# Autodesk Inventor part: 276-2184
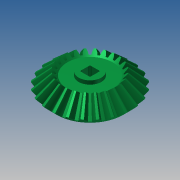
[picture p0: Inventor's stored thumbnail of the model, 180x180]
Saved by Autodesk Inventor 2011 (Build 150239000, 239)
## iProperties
Created: 2010-04
Part Number: 276-2184
Material: ABS Plastic
Document SubType Name: Modeling
Designer: Autodesk Inc.
Categories: <?xml version="1.0" encoding="UTF-16"?> <MemberInstance><Categories><FamilyTemplate><FamilyTemplateParameter ValueType="xs:double" Id="1" ObjectReferenceKey="da
Mass: 1.68349 g
Surface Area: 21.9898 cm^2
Volume: 1.58819 cm^3
Density: 1.06 g/cm^3
Catalog Web Link: http://www.vexrobotics.com/276-2184.html
Vendor: Innovation First, Inc.
CustomPartVersion: 1
Company: Autodesk Inc.
Author: Autodesk Inc.
Title: VEX Robotics Kit of Parts
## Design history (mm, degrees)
node "Top Point"
node "Mesh Plane2"
sketch "Teeth Body Sketch"
  geometry: L1 (0, 0)-(11.802, -13.598); L2 (11.802, -13.598)-(13.448, -11.952); L3 (13.448, -11.952)-(0, 0); L4 (12.7, -12.7)-(0, 0); L5 (7.629, -8.79)-(8.694, -7.726); L6 (11.802, -13.598)-(7.629, -8.79); L7 (13.448, -11.952)-(8.694, -7.726); L8 (0, -39.387)-(0, 6.564) reference; L9 (0, -12.7)-(13.448, -12.7)
  constraints: 16 end point, 4 point on line, 3 perpendicular, 2 collinear, 1 horizontal alignment, 1 vertical alignment
  dimensions: "d0" = 25.4 diameter of L4.start L8 (= da_de); "d1" = 23.60395 diameter of L1.end L8 (= da_dfe); "d2" = 26.89671 diameter of L2.end L8 (= da_dae); "d3" = 6.35 distance between parallel lines of L2 L5 (= da_b); "d4" = 11.95165 vertical distance of L2.end L1.start (= da_ve)
revolve "Teeth Body" sketch "Teeth Body Sketch" stored, may be unused: angle "d5" = 90 deg
node "Start Point"
node "Tooth Plane"
sketch "Start Sketch"
  geometry: L1 (0, -23.505)-(0, 10.645) reference; L2 (-0.4, -1.549)-(0.4, -1.549); A1 r 6.505 centre (-6.831, -2.533) between (-0.4, -1.549) and (-1.864, 1.669); A2 r 6.505 centre (6.831, -2.533) between (1.864, 1.669) and (0.4, -1.549); A3 r 19.717 centre (0, -17.961) between (1.864, 1.669) and (-1.864, 1.669); 1 further point
  constraints: 6 point on circle, 3 centre point, 3 symmetric about line, 2 end point, 1 coincident, 1 perpendicular, 1 other
  dimensions: "d7" = 6.50483 radius of A1 (= fd_rr); "d8" = 6.83059 horizontal distance of point (0, -17.961) A1.centre (= fd_x); "d9" = 15.42797 vertical distance of point (0, -17.961) A1.centre (= fd_y); "d57" = 19.71735 radius of A3 (= 0.5 x fd_dva + 0.3 x da_he); "d58" = 16.41111 distance from line of A3.centre L2 (= 0.5 x fd_dva - 1.12 x da_he)
node "End Point"
  node "End Plane"
sketch "3D Sketch Right"
  node "Helical Curve Right" dims "d65" = 127.62048 (computed from da_dm, da_delta, da_beta), "d66" = 31.5, "d67" = 25.4 (= da_de), "d68" = -45 deg (= -da_delta), "d69" = 4.57245 (computed from fd_loft, da_delta)
node "End Plane Right"
sketch "End Sketch Right"
  geometry: L1 (0, -18.196)-(0, 9.82) reference; L2 (-0.257, -0.975)-(0.257, -0.975); A1 r 4.169 centre (-4.378, -1.605) between (-0.257, -0.975) and (-1.195, 1.087); A2 r 4.169 centre (4.378, -1.605) between (1.195, 1.087) and (0.257, -0.975); A3 r 12.638 centre (0, -11.494) between (1.195, 1.087) and (-1.195, 1.087); 1 further point
  constraints: 6 point on circle, 3 centre point, 3 symmetric about line, 2 end point, 1 coincident, 1 perpendicular, 1 other
  dimensions: "d70" = 4.37817 horizontal distance of A3.centre A1.centre (computed from fd_x, fd_ratio); "d71" = 9.88879 vertical distance of point (0, -11.494) A1.centre (computed from fd_y, fd_ratio); "d72" = 4.16937 radius of A1 (computed from fd_rr, fd_ratio); "d73" = 10.51895 distance from line of point (0, -11.494) L2 (computed from d58, fd_ratio); "d74" = 12.63812 radius of A3 (computed from d57, fd_ratio)
feature "Loft Right" sketch "End Sketch Right" dims "d75" = 0, "d76" = 90 deg, "d77" = 0, "d78" = 90 deg, "d79" = 0, "d80" = 90 deg, "d85" = 20, "da_teethtype" = 0 [user parameter]
sketch "3D Sketch Left"
  node "Helical Curve Left" dims "d26" = 127.62048 (computed from da_dm, da_delta, da_beta), "d27" = 4.57245 (computed from fd_loft, da_delta), "d28" = 25.4 (= da_de), "d29" = -45 deg (= -da_delta)
node "End Plane Left"
sketch "End Sketch Left" dims "d56" = 6.1486 (derived)
  geometry: L1 (0, -31.428)-(0, 14.43) reference; L2 (-0.257, -0.973)-(0.257, -0.973); A1 r 4.169 centre (-4.378, -1.603) between (-0.257, -0.973) and (-1.195, 1.09); A2 r 4.169 centre (4.378, -1.603) between (1.195, 1.09) and (0.257, -0.973); A3 r 12.638 centre (0, -11.492) between (1.195, 1.09) and (-1.195, 1.09); 2 further points; 1 other entity
  constraints: 6 point on circle, 3 centre point, 3 symmetric about line, 2 end point, 1 coincident, 2 other
  dimensions: "d30" = 4.16937 radius of A1 (computed from fd_rr, fd_ratio); "d31" = 4.37817 horizontal distance of point (0, -11.492) A1.centre (computed from fd_x, fd_ratio); "d32" = 9.88879 vertical distance of A1.centre point (0, -11.492) (computed from fd_y, fd_ratio); "d61" = 12.63812 radius of A3 (computed from d57, fd_ratio); "d62" = 10.51895 distance from line of point (0, -11.492) L2 (computed from d58, fd_ratio)
feature "Loft Left" sketch "End Sketch Left" dims "d35" = 0, "d37" = 0, "d39" = 0, "d40" = 90 deg, "d63" = 90 deg, "d64" = 90 deg, "d84" = 10, "da_teethtype" = 0 [user parameter]
sketch "Body Sketch"
  geometry: L1 (0, -35.038)-(0, -19.531) reference; L2 (11.802, -13.598)-(7.629, -8.79) reference; L3 (7.629, -8.79)-(0, -8.79); L4 (11.802, -13.598)-(0, -13.598)
  constraints: 4 end point, 2 perpendicular, 2 point on line
revolve "Fix Body" sketch "Body Sketch" stored, may be unused: angle "d46" = 90 deg
sketch "Sketch6"
  geometry: L1 (12.7, -12.7)-(0, 0) reference; L2 (0, -37.8)-(0, 6.3) reference
feature "Pitch Diameter" sketch "Sketch6" dims angle "d47" = 90 deg
sketch "Sketch8"
  geometry: A1 r 7.629 centre (0, 0) between (0.287, 7.624) and (-0.287, 7.624) reference; A2 r 7.629 centre (0, 0) between (-0.287, 7.624) and (-1.696, 7.438) reference; A3 r 7.629 centre (0, 0) between (-1.696, 7.438) and (-2.25, 7.29) reference; A4 r 7.629 centre (0, 0) between (-2.25, 7.29) and (-3.564, 6.746) reference; A5 r 7.629 centre (0, 0) between (-3.564, 6.746) and (-4.06, 6.459) reference; A6 r 7.629 centre (0, 0) between (-4.06, 6.459) and (-5.188, 5.594) reference; A7 r 7.629 centre (0, 0) between (-5.188, 5.594) and (-5.594, 5.188) reference; A8 r 7.629 centre (0, 0) between (-5.594, 5.188) and (-6.459, 4.06) reference; A9 r 7.629 centre (0, 0) between (-6.459, 4.06) and (-6.746, 3.564) reference; A10 r 7.629 centre (0, 0) between (-6.746, 3.564) and (-7.29, 2.25) reference; A11 r 7.629 centre (0, 0) between (-7.29, 2.25) and (-7.438, 1.696) reference; A12 r 7.629 centre (0, 0) between (-7.438, 1.696) and (-7.624, 0.287) reference; A13 r 7.629 centre (0, 0) between (-7.624, 0.287) and (-7.624, -0.287) reference; A14 r 7.629 centre (0, 0) between (-7.624, -0.287) and (-7.438, -1.696) reference; A15 r 7.629 centre (0, 0) between (-7.438, -1.696) and (-7.29, -2.25) reference; A16 r 7.629 centre (0, 0) between (-7.29, -2.25) and (-6.746, -3.564) reference; A17 r 7.629 centre (0, 0) between (-6.746, -3.564) and (-6.459, -4.06) reference; A18 r 7.629 centre (0, 0) between (-6.459, -4.06) and (-5.594, -5.188) reference; A19 r 7.629 centre (0, 0) between (-5.594, -5.188) and (-5.188, -5.594) reference; A20 r 7.629 centre (0, 0) between (-5.188, -5.594) and (-4.06, -6.459) reference; A21 r 7.629 centre (0, 0) between (-4.06, -6.459) and (-3.564, -6.746) reference; A22 r 7.629 centre (0, 0) between (-3.564, -6.746) and (-2.25, -7.29) reference; A23 r 7.629 centre (0, 0) between (-2.25, -7.29) and (-1.696, -7.438) reference; A24 r 7.629 centre (0, 0) between (-1.696, -7.438) and (-0.287, -7.624) reference; A25 r 7.629 centre (0, 0) between (-0.287, -7.624) and (0.287, -7.624) reference; A26 r 7.629 centre (0, 0) between (0.287, -7.624) and (1.696, -7.438) reference; A27 r 7.629 centre (0, 0) between (1.696, -7.438) and (2.25, -7.29) reference; A28 r 7.629 centre (0, 0) between (2.25, -7.29) and (3.564, -6.746) reference; A29 r 7.629 centre (0, 0) between (3.564, -6.746) and (4.06, -6.459) reference; A30 r 7.629 centre (0, 0) between (4.06, -6.459) and (5.188, -5.594) reference; A31 r 7.629 centre (0, 0) between (5.188, -5.594) and (5.594, -5.188) reference; A32 r 7.629 centre (0, 0) between (5.594, -5.188) and (6.459, -4.06) reference; A33 r 7.629 centre (0, 0) between (6.459, -4.06) and (6.746, -3.564) reference; A34 r 7.629 centre (0, 0) between (6.746, -3.564) and (7.29, -2.25) reference; A35 r 7.629 centre (0, 0) between (7.29, -2.25) and (7.438, -1.696) reference; A36 r 7.629 centre (0, 0) between (7.438, -1.696) and (7.624, -0.287) reference; A37 r 7.629 centre (0, 0) between (7.624, -0.287) and (7.624, 0.287) reference; A38 r 7.629 centre (0, 0) between (7.624, 0.287) and (7.438, 1.696) reference; A39 r 7.629 centre (0, 0) between (7.438, 1.696) and (7.29, 2.25) reference; A40 r 7.629 centre (0, 0) between (7.29, 2.25) and (6.746, 3.564) reference; A41 r 7.629 centre (0, 0) between (6.746, 3.564) and (6.459, 4.06) reference; A42 r 7.629 centre (0, 0) between (6.459, 4.06) and (5.594, 5.188) reference; A43 r 7.629 centre (0, 0) between (5.594, 5.188) and (5.188, 5.594) reference; A44 r 7.629 centre (0, 0) between (5.188, 5.594) and (4.06, 6.459) reference; A45 r 7.629 centre (0, 0) between (4.06, 6.459) and (3.564, 6.746) reference; A46 r 7.629 centre (0, 0) between (3.564, 6.746) and (2.25, 7.29) reference; A47 r 7.629 centre (0, 0) between (2.25, 7.29) and (1.696, 7.438) reference; A48 r 7.629 centre (0, 0) between (1.696, 7.438) and (0.287, 7.624) reference
extrude "Extrusion1" cut sketch "Sketch8" distance "d90" = 0.3556; taper "d91" = -45 deg
sketch "Sketch9"
  geometry: A1 r 11.802 centre (0, 0) between (0.448, 11.793) and (-0.448, 11.793) reference; A2 r 11.802 centre (0, 0) between (-0.448, 11.793) and (-2.62, 11.508) reference; A3 r 11.802 centre (0, 0) between (-2.62, 11.508) and (-3.485, 11.276) reference; A4 r 11.802 centre (0, 0) between (-3.485, 11.276) and (-5.509, 10.437) reference; A5 r 11.802 centre (0, 0) between (-5.509, 10.437) and (-6.285, 9.989) reference; A6 r 11.802 centre (0, 0) between (-6.285, 9.989) and (-8.022, 8.656) reference; A7 r 11.802 centre (0, 0) between (-8.022, 8.656) and (-8.656, 8.022) reference; A8 r 11.802 centre (0, 0) between (-8.656, 8.022) and (-9.989, 6.285) reference; A9 r 11.802 centre (0, 0) between (-9.989, 6.285) and (-10.437, 5.509) reference; A10 r 11.802 centre (0, 0) between (-10.437, 5.509) and (-11.276, 3.485) reference; A11 r 11.802 centre (0, 0) between (-11.276, 3.485) and (-11.508, 2.62) reference; A12 r 11.802 centre (0, 0) between (-11.508, 2.62) and (-11.793, 0.448) reference; A13 r 11.802 centre (0, 0) between (-11.793, 0.448) and (-11.793, -0.448) reference; A14 r 11.802 centre (0, 0) between (-11.793, -0.448) and (-11.508, -2.62) reference; A15 r 11.802 centre (0, 0) between (-11.508, -2.62) and (-11.276, -3.485) reference; A16 r 11.802 centre (0, 0) between (-11.276, -3.485) and (-10.437, -5.509) reference; A17 r 11.802 centre (0, 0) between (-10.437, -5.509) and (-9.989, -6.285) reference; A18 r 11.802 centre (0, 0) between (-9.989, -6.285) and (-8.656, -8.022) reference; A19 r 11.802 centre (0, 0) between (-8.656, -8.022) and (-8.022, -8.656) reference; A20 r 11.802 centre (0, 0) between (-8.022, -8.656) and (-6.285, -9.989) reference; A21 r 11.802 centre (0, 0) between (-6.285, -9.989) and (-5.509, -10.437) reference; A22 r 11.802 centre (0, 0) between (-5.509, -10.437) and (-3.485, -11.276) reference; A23 r 11.802 centre (0, 0) between (-3.485, -11.276) and (-2.62, -11.508) reference; A24 r 11.802 centre (0, 0) between (-2.62, -11.508) and (-0.448, -11.793) reference; A25 r 11.802 centre (0, 0) between (-0.448, -11.793) and (0.448, -11.793) reference; A26 r 11.802 centre (0, 0) between (0.448, -11.793) and (2.62, -11.508) reference; A27 r 11.802 centre (0, 0) between (2.62, -11.508) and (3.485, -11.276) reference; A28 r 11.802 centre (0, 0) between (3.485, -11.276) and (5.509, -10.437) reference; A29 r 11.802 centre (0, 0) between (5.509, -10.437) and (6.285, -9.989) reference; A30 r 11.802 centre (0, 0) between (6.285, -9.989) and (8.022, -8.656) reference; A31 r 11.802 centre (0, 0) between (8.022, -8.656) and (8.656, -8.022) reference; A32 r 11.802 centre (0, 0) between (8.656, -8.022) and (9.989, -6.285) reference; A33 r 11.802 centre (0, 0) between (9.989, -6.285) and (10.437, -5.509) reference; A34 r 11.802 centre (0, 0) between (10.437, -5.509) and (11.276, -3.485) reference; A35 r 11.802 centre (0, 0) between (11.276, -3.485) and (11.508, -2.62) reference; A36 r 11.802 centre (0, 0) between (11.508, -2.62) and (11.793, -0.448) reference; A37 r 11.802 centre (0, 0) between (11.793, -0.448) and (11.793, 0.448) reference; A38 r 11.802 centre (0, 0) between (11.793, 0.448) and (11.508, 2.62) reference; A39 r 11.802 centre (0, 0) between (11.508, 2.62) and (11.276, 3.485) reference; A40 r 11.802 centre (0, 0) between (11.276, 3.485) and (10.437, 5.509) reference; A41 r 11.802 centre (0, 0) between (10.437, 5.509) and (9.989, 6.285) reference; A42 r 11.802 centre (0, 0) between (9.989, 6.285) and (8.656, 8.022) reference; A43 r 11.802 centre (0, 0) between (8.656, 8.022) and (8.022, 8.656) reference; A44 r 11.802 centre (0, 0) between (8.022, 8.656) and (6.285, 9.989) reference; A45 r 11.802 centre (0, 0) between (6.285, 9.989) and (5.509, 10.437) reference; A46 r 11.802 centre (0, 0) between (5.509, 10.437) and (3.485, 11.276) reference; A47 r 11.802 centre (0, 0) between (3.485, 11.276) and (2.62, 11.508) reference; A48 r 11.802 centre (0, 0) between (2.62, 11.508) and (0.448, 11.793) reference
extrude "Extrusion2" join sketch "Sketch9" distance "d92" = 1.1176; taper "d93" = -45 deg
sketch "Sketch10"
  geometry: C1 r 7.274 at (0, 0) reference; C2 r 3.632 at (0, 0)
  constraints: 1 centre point, 1 coincident
  dimensions: "d94" = 7.2644 diameter of C2
extrude "Extrusion3" join sketch "Sketch10" distance "d95" = 9.525; taper "d96" = 0 deg
extrude "Extrusion4" join sketch "Sketch10" distance "d97" = 1.1938; taper "d98" = 0 deg
sketch "Sketch11"
  geometry: L1 (1.612, 0.952)-(1.558, 1.007); L2 (1.558, 1.025)-(1.612, 1.079); L3 (1.612, 1.104)-(1.612, 1.079); L4 (1.558, 1.177)-(1.612, 1.231); L5 (1.612, 1.362)-(1.612, 1.231); L6 (1.232, 1.612)-(1.177, 1.558); L7 (1.159, 1.558)-(1.105, 1.612); L8 (1.079, 1.612)-(1.105, 1.612); L9 (1.232, 1.612)-(1.362, 1.612); L10 (1.612, 0.952)-(1.612, -0.952); L11 (1.558, -1.007)-(1.612, -0.952); L12 (1.612, 1.104)-(1.558, 1.159); L13 (1.079, 1.612)-(1.025, 1.558); L14 (-1.362, 1.612)-(-1.231, 1.612); L15 (-1.177, 1.558)-(-1.231, 1.612); L16 (1.007, 1.558)-(0.952, 1.612); L17 (-0.952, 1.613)-(0.952, 1.612); L18 (-0.952, 1.613)-(-1.007, 1.558); L19 (-1.024, 1.558)-(-1.079, 1.612); L20 (-1.104, 1.613)-(-1.079, 1.612); L21 (-1.104, 1.613)-(-1.159, 1.558); L22 (1.613, -1.079)-(1.558, -1.024); L23 (1.613, -1.079)-(1.612, -1.105); L24 (1.558, -1.159)-(1.612, -1.105); L25 (1.613, -1.231)-(1.558, -1.177); L26 (1.613, -1.231)-(1.612, -1.362); L27 (1.362, -1.612)-(1.231, -1.612); L28 (1.177, -1.558)-(1.231, -1.612); L29 (1.104, -1.613)-(1.079, -1.612); L30 (1.024, -1.558)-(1.079, -1.612); L31 (0.952, -1.613)-(1.007, -1.558); L32 (0.952, -1.613)-(-0.952, -1.612); L33 (1.104, -1.613)-(1.159, -1.558); L34 (-1.007, -1.558)-(-0.952, -1.612); L35 (-1.079, -1.612)-(-1.025, -1.558); L36 (-1.079, -1.612)-(-1.105, -1.612); L37 (-1.159, -1.558)-(-1.105, -1.612); L38 (-1.232, -1.612)-(-1.177, -1.558); L39 (-1.612, -0.952)-(-1.558, -1.007); L40 (-1.558, -1.025)-(-1.612, -1.079); L41 (-1.612, -1.104)-(-1.612, -1.079); L42 (-1.612, -1.104)-(-1.558, -1.159); L43 (-1.558, -1.177)-(-1.612, -1.231); L44 (-1.612, -1.362)-(-1.612, -1.231); L45 (-1.232, -1.612)-(-1.362, -1.612); L46 (-1.612, -0.952)-(-1.612, 0.952); L47 (-1.558, 1.007)-(-1.612, 0.952); L48 (-1.613, 1.079)-(-1.558, 1.024); L49 (-1.613, 1.079)-(-1.612, 1.105); L50 (-1.558, 1.159)-(-1.612, 1.105); L51 (-1.613, 1.231)-(-1.558, 1.177); L52 (-1.613, 1.231)-(-1.612, 1.362); A1 r 0.013 centre (1.567, 1.016) between (1.558, 1.025) and (1.558, 1.007); A2 r 0.013 centre (1.567, 1.168) between (1.558, 1.177) and (1.558, 1.159); A3 r 0.25 centre (1.362, 1.362) between (1.612, 1.362) and (1.362, 1.612); A4 r 0.013 centre (1.168, 1.567) between (1.159, 1.558) and (1.177, 1.558); A5 r 0.012 centre (-1.016, 1.566) between (-1.024, 1.558) and (-1.007, 1.558); A6 r 0.012 centre (-1.168, 1.566) between (-1.177, 1.558) and (-1.159, 1.558); A7 r 0.013 centre (1.016, 1.567) between (1.007, 1.558) and (1.025, 1.558); A8 r 0.012 centre (1.566, -1.016) between (1.558, -1.007) and (1.558, -1.024); A9 r 0.013 centre (1.567, -1.168) between (1.558, -1.159) and (1.558, -1.177); A10 r 0.25 centre (1.362, -1.362) between (1.362, -1.612) and (1.612, -1.362); A11 r 0.012 centre (1.168, -1.566) between (1.177, -1.558) and (1.159, -1.558); A12 r 0.012 centre (1.016, -1.566) between (1.024, -1.558) and (1.007, -1.558); A13 r 0.013 centre (-1.016, -1.567) between (-1.007, -1.558) and (-1.025, -1.558); A14 r 0.013 centre (-1.168, -1.567) between (-1.159, -1.558) and (-1.177, -1.558); A15 r 0.013 centre (-1.567, -1.168) between (-1.558, -1.177) and (-1.558, -1.159); A16 r 0.013 centre (-1.567, -1.016) between (-1.558, -1.025) and (-1.558, -1.007); A17 r 0.25 centre (-1.362, -1.362) between (-1.612, -1.362) and (-1.362, -1.612); A18 r 0.25 centre (-1.362, 1.362) between (-1.362, 1.612) and (-1.612, 1.362); A19 r 0.013 centre (-1.567, 1.168) between (-1.558, 1.159) and (-1.558, 1.177); A20 r 0.012 centre (-1.566, 1.016) between (-1.558, 1.007) and (-1.558, 1.024); 1 further point
  constraints: 104 end point, 40 point on circle, 20 centre point
feature "iFeature2:1" sketch "Sketch11"
sketch "Sketch12"
  geometry: L1 (10.684, -14.716)-(-10.684, -14.716) reference; L2 (-3.632, -14.716)-(-3.632, -18.671) reference; L3 (-10.684, -14.716)-(-7.221, -10.702); L4 (-7.221, -10.702)-(-3.632, -10.702); L5 (-3.632, -10.702)-(-3.632, -14.716); L6 (0, -22.405)-(0, 3.734) reference; 1 further point
  constraints: 6 end point, 2 perpendicular
  dimensions: "d99" = 49.21 deg angle of L1 L3; "d100" = 4.0132 distance between parallel lines of L1 L4
revolve "Revolution3" sketch "Sketch12" stored, may be unused: angle "d101" = 90 deg
sketch "Sketch13"
  geometry: L1 (-3.632, -10.702)-(-3.632, -18.671) reference; L2 (-10.684, -14.716)-(-3.632, -14.687); 1 further point
  constraints: 2 end point, 1 midpoint
feature "Rib1" sketch "Sketch13" dims "d102" = 2.54, "d103" = 1.27, "d104" = 0
pattern_circular "Circular Pattern4" dims angle "d106" = 360 deg
body "Solid1"
feature "Loft" dims "d17" = 0, "d18" = 90 deg, "d19" = 0, "d20" = 90 deg, "d89" = 0, "da_teethtype" = 0 [user parameter]
pattern_circular "Circular Pattern" dims angle "d22" = 360 deg, "d88" = 0, "da_teethtype" = 0 [user parameter]
pattern_circular "Circular Pattern Right" dims angle "d82" = 360 deg, "da_teethtype" = 0 [user parameter]
pattern_circular "Circular Pattern Left" dims angle "d42" = 360 deg, "da_teethtype" = 0 [user parameter]
sketch "End Sketch"
  geometry: L1 (0, -15.359)-(0, 6.983) reference; L2 (-0.257, -0.975)-(0.257, -0.975); A1 r 4.169 centre (-4.378, -1.605) between (-0.257, -0.975) and (-1.195, 1.087); A2 r 4.169 centre (4.378, -1.605) between (1.195, 1.087) and (0.257, -0.975); A3 r 12.638 centre (0, -11.494) between (1.195, 1.087) and (-1.195, 1.087); 1 further point
  constraints: 6 point on circle, 3 centre point, 3 symmetric about line, 2 end point, 1 coincident, 1 other
  dimensions: "d12" = 4.16937 radius of A1 (computed from fd_rr, fd_ratio); "d15" = 4.37817 horizontal distance of A1.centre point (0, -11.494) (computed from fd_x, fd_ratio); "d16" = 9.88879 vertical distance of A1.centre point (0, -11.494) (computed from fd_y, fd_ratio); "d59" = 12.63812 radius of A3 (computed from d57, fd_ratio); "d60" = 10.51895 distance from line of A3.centre L2 (computed from d58, fd_ratio)
body "Srf1"
other parameters: "da_b" = 6.35 [user parameter; used in 2 equation terms], "da_de" = 25.4 [user parameter; used in 4 equation terms], "da_dae" = 26.89671 [user parameter; used in 2 equation terms], "da_dfe" = 23.60395 [user parameter; used in 1 equation term], "da_le" = 17.96051 [user parameter; used in 1 equation term], "da_omega" = 90 deg [user parameter; used in 1 equation term], "da_beta" = 0 [user parameter; used in 2 equation terms], "da_delta" = 45 deg [user parameter; used in 8 equation terms], "da_alpha" = 20 deg [user parameter; used in 2 equation terms], "da_he" = 2.32833 [user parameter; used in 4 equation terms], "da_ve" = 11.95165 [user parameter; used in 1 equation term], "fd_dv" = 35.92102 (computed from da_de, da_delta) [user parameter; used in 1 equation term], "fd_dva" = 38.03769 (computed from da_dae, da_delta) [user parameter; used in 3 equation terms], "fd_dvb" = 33.75472 (computed from fd_dv, da_alpha) [user parameter; used in 2 equation terms], "da_zv" = 339.41125 [user parameter; used in 1 equation term], "fd_loft" = 6.46642 (= da_b + 0.05 x da_he) [user parameter; used in 4 equation terms], "fd_ratio" = 6.40965 (computed from da_le, fd_loft) [user parameter; used in 15 equation terms], "fd_rr" = 6.50483 (computed from fd_dd, fd_dvb) [user parameter; used in 6 equation terms], "fd_angle" = 0.4628 (computed from da_zv) [user parameter; used in 4 equation terms], "fd_x1" = 0.83092 (computed from da_dvw, fd_angle) [user parameter; used in 1 equation term], "fd_y1" = 17.94128 (computed from da_dvw, fd_angle) [user parameter; used in 1 equation term], "fd_x2" = 5.99967 (computed from fd_rr, fd_angle2, fd_angle) [user parameter; used in 1 equation term], "fd_y2" = 2.51331 (computed from fd_rr, fd_angle2, fd_angle) [user parameter; used in 1 equation term], "fd_x" = 6.83059 (= fd_x1 + fd_x2) [user parameter; used in 4 equation terms], "fd_y" = 15.42797 (= fd_y1 - fd_y2) [user parameter; used in 4 equation terms], "fd_angle2" = 3.50419 (computed from fd_dvb, fd_dd, da_alpha) [user parameter; used in 2 equation terms], "fd_dd" = 36.17502 (= fd_dva - 0.8 x da_he) [user parameter; used in 2 equation terms], "da_dvw" = 35.92102 [user parameter; used in 2 equation terms], "d11" = 6.46642 (= fd_loft), "da_dm" = 20.90987 [user parameter; used in 2 equation terms], "da_x" = 0 [user parameter], "da_m" = 1.05833 [user parameter], "d48" = 0, "d49" = 0, "d50" = 90 deg (= da_omega), "d51" = 7.5 deg (computed from da_z), "d52" = 0, "d53" = 0, "d54" = 0
